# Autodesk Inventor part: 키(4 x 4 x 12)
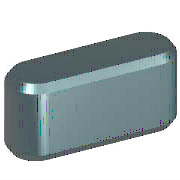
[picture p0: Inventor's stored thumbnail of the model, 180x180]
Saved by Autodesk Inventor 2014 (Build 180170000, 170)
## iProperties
IsCustomPart: 0
Created: 2009-02
Part Number: 키(4 x 4 x 12)
Material: 강, 연강
Description: 키 및 해당 키홈
Document SubType Name: Modeling
Standard: KS B 1311
Designer: KYOUNG IL JANG
Standards Organization: KS
Language: ko-KR
Size Designation: 4 x 4 x 12
Categories: <MemberInstance><Categories><Category DisplayName="샤프트 부품" InternalName="7f7aeb1f-a693-4053-b835-cee3144e0d98" Mnemonic="SHFT"><Category DisplayName="키" Interna
Density: 7.86 g/cm^3
Mass: 1.38739 g
Surface Area: 1.94869 cm^2
Volume: 0.176513 cm^3
Appearance: 강철
Author: KYOUNG IL JANG
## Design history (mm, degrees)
workplane "Work Plane1"
workplane "Work Plane2"
sketch "스케치1"
  geometry: L1 (2, 2)-(10, 2); L2 (10, -2)-(2, -2); L3 (0, 9.4)-(0, -7.4) reference; L4 (-5, 0)-(30, 0) reference; L5 (12, 0)-(12, 7); A1 r 2 centre (2, 0) between (2, 2) and (2, -2); A2 r 2 centre (10, 0) between (10, -2) and (10, 2)
  constraints: 6 end point, 5 point on circle, 4 tangent, 3 point on line, 2 centre point, 1 horizontal, 1 parallel, 1 perpendicular
  dimensions: "d0" = 2 radius of A1 (= 0.5 x PB); "d13" = 2 radius of A2 (= 0.5 x PB); "d14" = 12 distance between parallel lines of L5 L3 (= NLG)
extrude "본체1" new body sketch "스케치1" taper "d3" = 0 deg; stored distance "d4" = 10
workplane "Work Plane3"
body "Solid1"
chamfer "모따기1" distance "d8" = 0.25 (= PHH); stored, may be unused: second distance "d9" = 0.25 (= PHH), angle "d15" = 45 deg
other parameters: "d1" = -2.5 (= -PNT), "d2" = 1.5 (= PH - PNT), "NLG" = 12 [user parameter; used in 3 equation terms], "PB" = 4 [user parameter; used in 2 equation terms], "PNT" = 2.5 [user parameter; used in 2 equation terms], "PH" = 4 [user parameter; used in 1 equation term], "PHH" = 0.25 [user parameter; used in 2 equation terms], "d10" = 0, "d16" = 0, "d17" = 0, "d18" = 0, "PLB2" = 12 (= NLG) [user parameter], "WDMAX" = 12 [user parameter], "PLB1" = 12 (= NLG) [user parameter], "RR" = 0.08 [user parameter], "PUEB" = 1.8 [user parameter]
